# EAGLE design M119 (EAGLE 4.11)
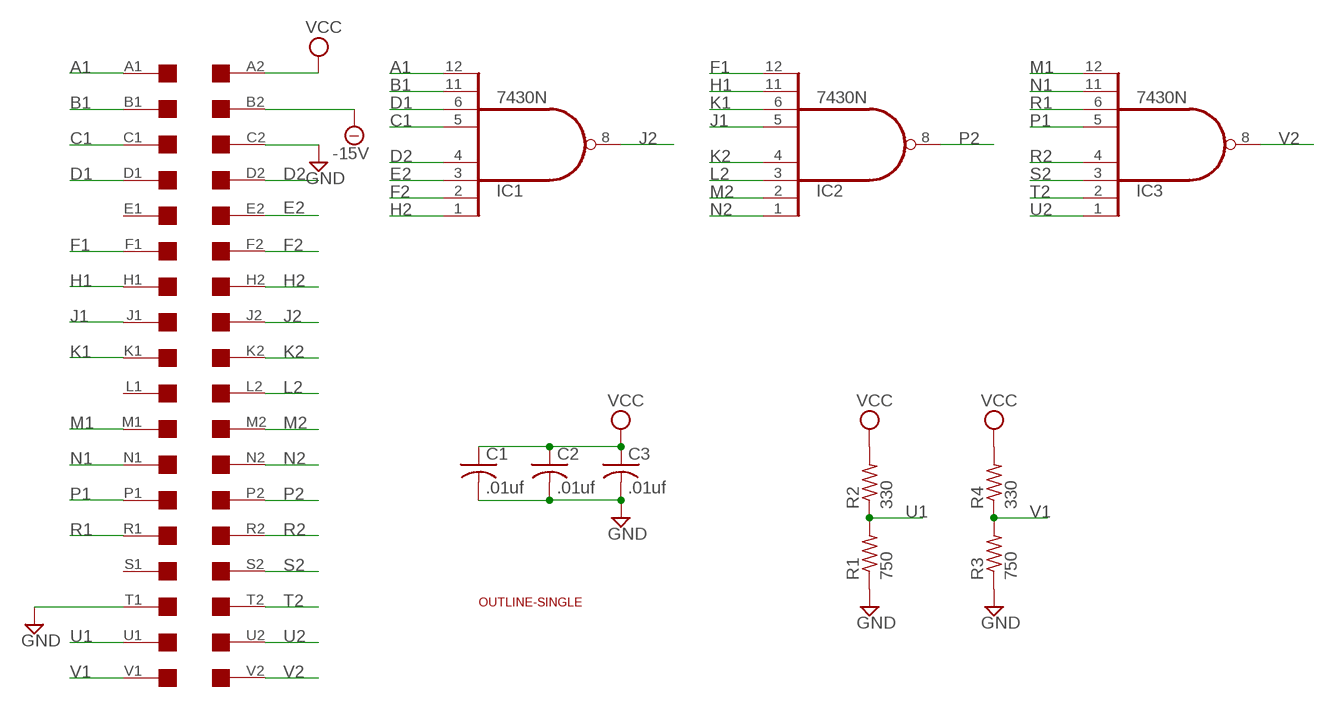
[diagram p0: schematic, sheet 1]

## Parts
C1  .01uf  C-US050-025X075  [C050-025X075]
C2  .01uf  C-US050-025X075  [C050-025X075]
C3  .01uf  C-US050-025X075  [C050-025X075]
IC1  7430N  [DIL14]
IC2  7430N  [DIL14]
IC3  7430N  [DIL14]
R1  750  R-US_0207/10  [0207/10]
R2  330  R-US_0207/10  [0207/10]
R3  750  R-US_0207/10  [0207/10]
R4  330  R-US_0207/10  [0207/10]
U$1  OUTLINE-SINGLE  [SINGLE]
U$4  SINGLE  [EDGE-CON2]

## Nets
-15V: U$4.B2
A1: IC1.12(I7) U$4.A1
B1: IC1.11(I6) U$4.B1
C1: IC1.5(I4) U$4.C1
D1: IC1.6(I5) U$4.D1
D2: IC1.4(I3) U$4.D2
E2: IC1.3(I2) U$4.E2
F1: IC2.12(I7) U$4.F1
F2: IC1.2(I1) U$4.F2
GND: C1.2 C2.2 C3.2 R1.1 R3.1 U$4.C2 U$4.T1
H1: IC2.11(I6) U$4.H1
H2: IC1.1(I0) U$4.H2
J1: IC2.5(I4) U$4.J1
J2: IC1.8(O) U$4.J2
K1: IC2.6(I5) U$4.K1
K2: IC2.4(I3) U$4.K2
L2: IC2.3(I2) U$4.L2
M1: IC3.12(I7) U$4.M1
M2: IC2.2(I1) U$4.M2
N1: IC3.11(I6) U$4.N1
N2: IC2.1(I0) U$4.N2
P1: IC3.5(I4) U$4.P1
P2: IC2.8(O) U$4.P2
R1: IC3.6(I5) U$4.R1
R2: IC3.4(I3) U$4.R2
S2: IC3.3(I2) U$4.S2
T2: IC3.2(I1) U$4.T2
U1: R1.2 R2.1 U$4.U1
U2: IC3.1(I0) U$4.U2
V1: R3.2 R4.1 U$4.V1
V2: IC3.8(O) U$4.V2
VCC: C1.1 C2.1 C3.1 R2.2 R4.2 U$4.A2
Unconnected: U$4.E1 U$4.L1 U$4.S1

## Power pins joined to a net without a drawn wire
GND: IC1.7(GND) IC2.7(GND) IC3.7(GND)
VCC: IC1.14(VCC) IC2.14(VCC) IC3.14(VCC)

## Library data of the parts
C1-C3 = rcl:C-US: CAPACITOR, American symbol
IC1-IC3 = 74xx-us:74*30: 8-input NAND gate
R1-R4 = rcl:R-US_: RESISTOR, American symbol
U$1 = dec-con:OUTLINE-*: Board outlines for DEC boards.
U$4 = dec-con:SINGLE: Single-Height DEC board

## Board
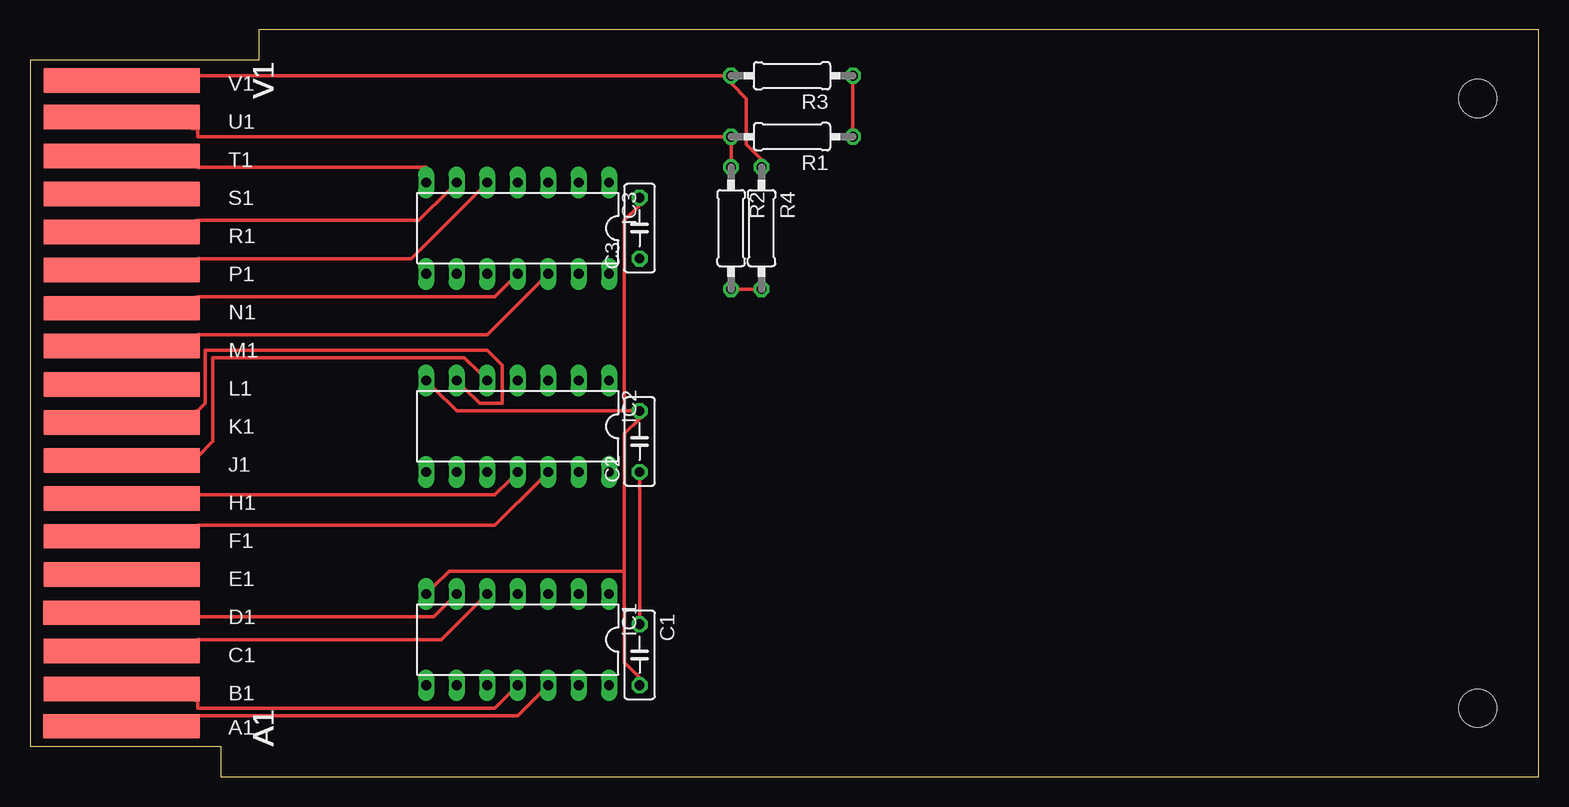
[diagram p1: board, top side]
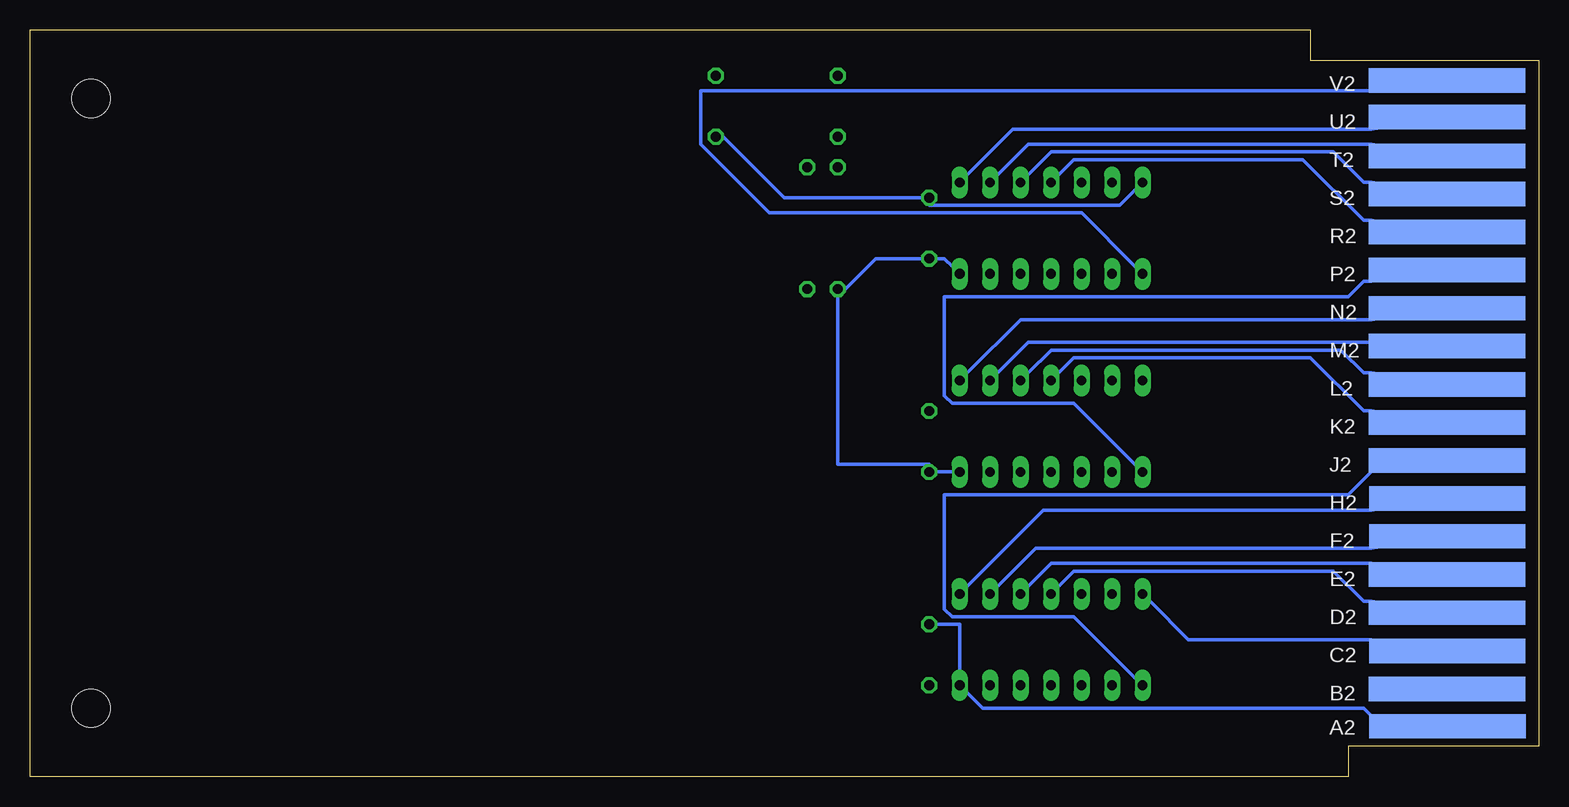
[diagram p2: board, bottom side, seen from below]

Size 125.73 x 62.23 mm. Coordinates in mm from the lower left corner, seen from the top.
Copper layers (1*16): Top 0.035mm / dielectric 1.5mm / Bottom 0.035mm
Design rules "10mils": minimum track width 12mil, minimum drill 28mil, track to track 10mil, track to pad 10mil, pad to pad 10mil, via to via 10mil, smd to smd 10mil, copper to edge 25mil, drill to drill 10mil, minimum pad ring 10mil, minimum via ring 8mil, stop-mask expansion 0mil, vias tented up to drill 0mil, thermal gap 10mil

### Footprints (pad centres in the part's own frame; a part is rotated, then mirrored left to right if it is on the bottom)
C050-025X075 = drill 0.813 octagon: 1 -2.54,0; 2 2.54,0
DIL14 = drill 0.813 long: 1 -7.62,-3.81; 2 -5.08,-3.81; 3 -2.54,-3.81; 4 0,-3.81; 5 2.54,-3.81; 6 5.08,-3.81; 7 7.62,-3.81; 8 7.62,3.81; 9 5.08,3.81; 10 2.54,3.81; 11 0,3.81; 12 -2.54,3.81; 13 -5.08,3.81; 14 -7.62,3.81
0207/10 = drill 0.813 octagon: 1 -5.08,0; 2 5.08,0
SINGLE = hole 3.175: 120.65,56.515; 120.65,5.715
EDGE-CON2 = smd 13.017 x 2.032: A1 7.633,4.207; B1 7.639,7.327; C1 7.636,10.489; D1 7.633,13.665; E1 7.642,16.84; F1 7.642,20.041; H1 7.642,23.19; J1 7.642,26.34; K1 7.642,29.515; L1 7.642,32.69; M1 7.642,35.89; N1 7.642,39.04; P1 7.642,42.24; R1 7.642,45.39; S1 7.642,48.565; T1 7.642,51.74; U1 7.642,54.966; V1 7.642,58.026 | smd 13.017 x 2.032 bottom: A2 7.614,4.207; B2 7.642,7.328; C2 7.617,10.49; D2 7.642,13.665; E2 7.642,16.84; F2 7.617,20.041; H2 7.617,23.19; J2 7.642,26.34; K2 7.642,29.515; L2 7.642,32.69; M2 7.642,35.89; N2 7.642,39.04; P2 7.642,42.24; R2 7.642,45.39; S2 7.642,48.565; T2 7.642,51.74; U2 7.642,54.966; V2 7.642,58.026

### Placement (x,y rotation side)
C1  50.8,10.16 270 top
C2  50.8,27.94 90 top
C3  50.8,45.72 90 top
IC1  40.64,11.43 180 top
IC2  40.64,29.21 180 top
IC3  40.64,45.72 180 top
R1  63.5,53.34 180 top
R2  58.42,45.72 270 top
R3  63.5,58.42 180 top
R4  60.96,45.72 270 top
U$1  0,0 0 top
U$4  0,0 0 top

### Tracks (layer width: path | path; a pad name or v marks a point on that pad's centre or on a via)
A1
  Top 0.305: IC1.12 42.55,6.99 40.64,5.08 13.97,5.08 U$4.A1
B1
  Top 0.305: IC1.11 40.01,6.99 38.74,5.71 13.97,5.71 13.97,6.35 U$4.B1
C1
  Top 0.305: IC1.5 37.47,14.61 34.29,11.43 13.97,11.43 U$4.C1
D1
  Top 0.305: IC1.6 34.93,14.61 33.66,13.34 13.97,13.34 U$4.D1
D2
  Bottom 0.305: IC1.4 40.01,15.88 38.74,17.14 17.15,17.14 14.61,14.61 13.97,14.61 U$4.D2
E2
  Bottom 0.305: IC1.3 42.55,15.88 40.64,17.78 13.97,17.78 U$4.E2
F1
  Top 0.305: IC2.12 42.55,24.77 38.74,20.95 13.97,20.95 U$4.F1
F2
  Bottom 0.305: IC1.2 45.09,15.88 41.91,19.05 13.97,19.05 U$4.F2
GND
  Top 0.305: R1.1 68.58,53.98 68.58,57.78 R3.1 | 49.53,17.14 49.53,28.57 50.8,29.84 C2.2 50.17,30.48 49.53,30.48 | 49.53,17.14 49.53,9.53 50.8,8.26 C1.2 | 49.53,30.48 35.56,30.48 33.66,32.38 IC2.7 | 49.53,30.48 49.53,46.35 50.8,47.62 C3.2 | U$4.T1 13.97,50.8 33.02,50.8 IC3.7 | 49.53,17.14 34.93,17.14 33.66,15.88 IC1.7
  Bottom 0.305: IC1.7 32.39,14.61 29.21,11.43 13.97,11.43 U$4.C2 | IC3.7 33.66,48.9 34.93,47.62 50.8,47.62 C3.2 51.44,48.26 62.87,48.26 67.95,53.34 R1.1
H1
  Top 0.305: IC2.11 40.01,24.77 38.74,23.5 13.97,23.5 U$4.H1
H2
  Bottom 0.305: IC1.1 47.63,15.88 41.28,22.23 13.97,22.23 U$4.H2
J1
  Top 0.305: IC2.5 37.47,33.66 36.2,34.92 15.24,34.92 15.24,27.94 13.97,26.67 U$4.J1
J2
  Bottom 0.305: IC1.8 33.66,8.26 38.74,13.34 48.9,13.34 49.53,13.97 49.53,23.5 15.88,23.5 13.97,25.4 U$4.J2
K1
  Top 0.305: IC2.6 36.2,32.38 37.47,31.11 39.37,31.11 39.37,34.29 38.1,35.56 14.61,35.56 14.61,31.11 13.97,30.48 U$4.K1
K2
  Bottom 0.305: IC2.4 40.01,33.66 38.74,34.92 19.05,34.92 14.61,30.48 13.97,30.48 U$4.K2
L2
  Bottom 0.305: IC2.3 42.55,33.66 40.64,35.56 16.51,35.56 14.61,33.66 13.97,33.66 U$4.L2
M1
  Top 0.305: IC3.12 42.55,41.27 38.1,36.83 13.97,36.83 U$4.M1
M2
  Bottom 0.305: IC2.2 45.09,33.66 42.55,36.2 13.97,36.2 U$4.M2
N1
  Top 0.305: IC3.11 40.01,41.27 38.74,40.01 13.97,40.01 U$4.N1
N2
  Bottom 0.305: IC2.1 47.63,33.66 43.18,38.1 13.97,38.1 U$4.N2
P1
  Top 0.305: IC3.5 37.47,48.9 31.75,43.18 13.97,43.18 U$4.P1
P2
  Bottom 0.305: IC2.8 33.66,26.04 38.74,31.11 48.9,31.11 49.53,31.75 49.53,40.01 15.88,40.01 14.61,41.27 13.97,41.27 U$4.P2
R1
  Top 0.305: IC3.6 34.93,48.9 32.39,46.35 13.97,46.35 U$4.R1
R2
  Bottom 0.305: IC3.4 40.01,50.16 38.74,51.44 19.69,51.44 14.61,46.35 13.97,46.35 U$4.R2
S2
  Bottom 0.305: IC3.3 42.55,50.16 40.64,52.07 17.15,52.07 14.61,49.53 13.97,49.53 U$4.S2
T2
  Bottom 0.305: IC3.2 45.09,50.16 42.55,52.7 13.97,52.7 U$4.T2
U1
  Top 0.305: R2.1 58.42,51.44 58.42,52.7 R1.2 57.79,53.34 13.97,53.34 13.97,53.98 U$4.U1
U2
  Bottom 0.305: IC3.1 47.63,50.16 43.82,53.98 13.97,53.98 U$4.U2
V1
  Top 0.305: R4.1 60.96,51.44 59.69,52.7 59.69,56.52 58.42,57.78 R3.2 57.79,58.42 13.97,58.42 U$4.V1
V2
  Bottom 0.305: IC3.8 33.66,42.55 38.1,46.99 64.14,46.99 69.85,52.7 69.85,57.15 13.97,57.15 U$4.V2
VCC
  Top 0.305: R2.2 59.06,40.64 60.33,40.64 R4.2 | C2.1 50.8,24.77 50.8,13.34 C1.1
  Bottom 0.305: IC3.14 48.9,42.55 49.53,43.18 50.17,43.18 C3.1 51.44,43.18 55.25,43.18 57.79,40.64 R2.2 58.42,40.01 58.42,26.04 50.8,26.04 C2.1 50.17,25.4 48.9,25.4 IC2.14 | C1.1 50.17,12.7 48.26,12.7 48.26,8.89 IC1.14 47.63,6.99 46.36,5.71 14.61,5.71 13.97,5.08 U$4.A2

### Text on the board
tNames: V1 | V1 | V1 | V1 | V1 | V1 | V1 | V1 | V1 | V1 | V1 | V1 | V1 | V1 | V1 | V1 | V1 | V1 | V1 | V1 | V1 | V1 | V1 | V1 | V1 | V1 | V1 | V1 | V1 | V1 | V1 | V1 | A1 | A1 | A1 | A1 | A1 | A1 | A1 | A1 | A1 | A1 | A1 | A1 | A1 | A1 | A1 | A1 | A1 | A1 | A1 | A1 | A1 | A1 | A1 | A1 | A1 | A1 | A1 | A1 | A1 | A1 | A1 | A1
